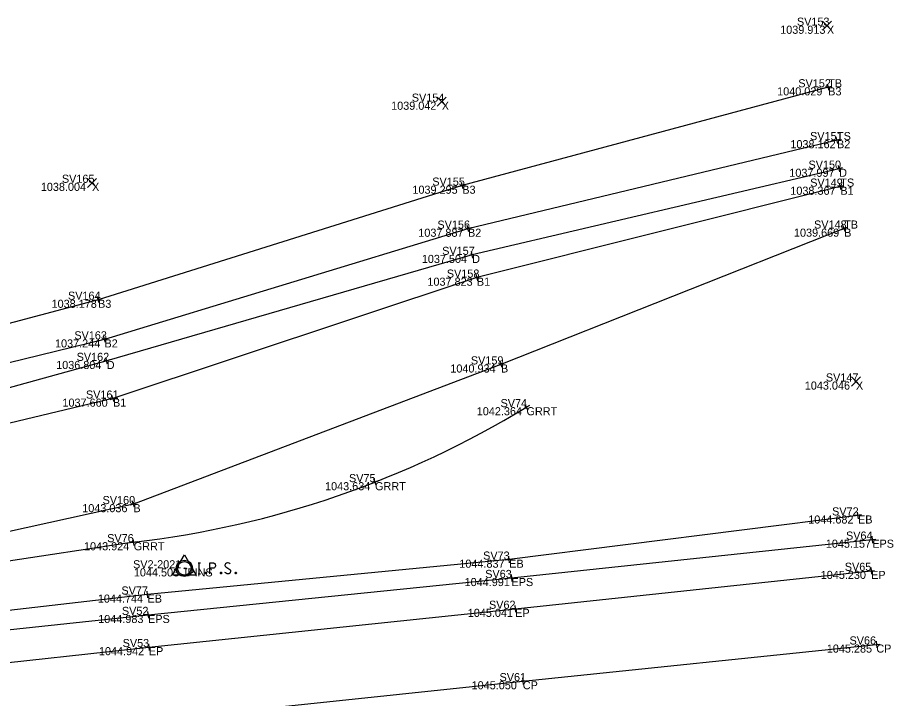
# Model space of a CAD drawing. Extents: x 1542529 to 1609210, y 587215 to 645373.
# Drawn here: x 1609069.9 to 1609199.5, y 645271.7 to 645372.6 of the extents above; entities that cross this region are included whole.
import ezdxf

# ---------------------------------------------------------------- set-up
doc = ezdxf.new("R2010")
doc.units = 0
for name, color, linetype in [('DR_X_Ditch', 7, 'Continuous'), ('PV_X_COP', 7, 'Continuous'), ('PV_X_EOP', 7, 'Continuous'), ('PV_X_Shoulder', 7, 'Continuous'), ('PV_X_Shoulder_Aggregate', 7, 'Continuous'), ('RD_X_GR_Rt', 7, 'Continuous'), ('SV_Control_Point', 7, 'Continuous'), ('SV_P_Mon_Cells_Set', 7, 'Continuous'), ('SV_X_Random_Point', 7, 'Continuous'), ('SV_X_Shot_Marker', 7, 'Continuous'), ('SV_X_Text_Comment', 7, 'Continuous'), ('SV_X_Text_Description', 7, 'Continuous'), ('SV_X_Text_Elevation', 7, 'Continuous'), ('SV_X_Text_Name', 7, 'Continuous'), ('SV_X_Toe_of_Slope', 7, 'Continuous'), ('SV_X_Top_of_Bank', 7, 'Continuous')]:
    doc.layers.add(name, color=color, linetype=linetype)

msp = doc.modelspace()

# ---------------------------------------------------------------- linework, layer by layer
at = {"layer": 'DR_X_Ditch'}
msp.add_lwpolyline([(1609191.48, 645350.17), (1609137.17, 645337.41), (1609083.09, 645321.71), (1609033.27, 645307.94), (1608983.73, 645297.77), (1608971.61, 645296.9)], dxfattribs=at)
at = {"layer": 'PV_X_COP'}
msp.add_lwpolyline([(1608977.96, 645256.77), (1609036.2, 645262.81), (1609089.9, 645268.52), (1609144.66, 645274.29), (1609196.98, 645279.72)], dxfattribs=at)
at = {"layer": 'PV_X_EOP'}
msp.add_lwpolyline([(1608980.54, 645267.46), (1609035.11, 645273.39), (1609089.32, 645279.34), (1609143.54, 645285.01), (1609196.2, 645290.63)], dxfattribs=at)
at = {"layer": 'PV_X_Shoulder'}
msp.add_lwpolyline([(1608982.3, 645272.44), (1609034.56, 645278.3), (1609089.21, 645284.1), (1609142.99, 645289.57), (1609196.38, 645295.25)], dxfattribs=at)
at = {"layer": 'PV_X_Shoulder_Aggregate'}
msp.add_lwpolyline([(1609194.27, 645298.83), (1609142.65, 645292.29), (1609089.13, 645287.12), (1609034.36, 645280.82), (1608983.09, 645274.8)], dxfattribs=at)
at = {"layer": 'RD_X_GR_Rt'}
msp.add_line((1609087.09, 645294.87), (1609034.27, 645286.84), dxfattribs=at)
msp.add_arc((1609070.49, 645437.62), 143.71, 276.6306, 301.327, dxfattribs=at)
at = {"layer": 'SV_Control_Point'}
for p, q in [((1609092.85, 645290), (1609094.58, 645293)), ((1609094.58, 645293), (1609096.32, 645290)), ((1609094.58, 645291), (1609094.58, 645291)), ((1609096.32, 645290), (1609092.85, 645290))]:
    msp.add_line(p, q, dxfattribs=at)
msp.add_circle((1609094.58, 645291), 1, dxfattribs=at)
at = {"layer": 'SV_P_Mon_Cells_Set'}
for points in [[(1609094.68, 645291.04), (1609094.7, 645291.04)], [(1609094.68, 645290.96), (1609094.7, 645290.96)], [(1609094.69, 645290.96), (1609094.69, 645291.04)], [(1609094.74, 645290.97), (1609094.74, 645290.97), (1609094.75, 645290.96), (1609094.75, 645290.96), (1609094.75, 645290.96), (1609094.75, 645290.96), (1609094.74, 645290.96), (1609094.74, 645290.96), (1609094.74, 645290.96), (1609094.74, 645290.96), (1609094.74, 645290.96), (1609094.74, 645290.96), (1609094.74, 645290.97)], [(1609094.77, 645290.96), (1609094.77, 645291.04), (1609094.8, 645291.04), (1609094.8, 645291.03), (1609094.81, 645291.03), (1609094.81, 645291.03), (1609094.81, 645291.03), (1609094.81, 645291.03), (1609094.81, 645291.02), (1609094.81, 645291.02), (1609094.81, 645291.01), (1609094.81, 645291.01), (1609094.81, 645291.01), (1609094.81, 645291), (1609094.81, 645291), (1609094.81, 645291), (1609094.8, 645291), (1609094.8, 645291), (1609094.77, 645291)], [(1609094.85, 645290.97), (1609094.86, 645290.97), (1609094.86, 645290.96), (1609094.86, 645290.96), (1609094.86, 645290.96), (1609094.86, 645290.96), (1609094.86, 645290.96), (1609094.85, 645290.96), (1609094.85, 645290.96), (1609094.85, 645290.96), (1609094.85, 645290.96), (1609094.85, 645290.96), (1609094.85, 645290.97)], [(1609094.92, 645291.03), (1609094.92, 645291.03), (1609094.92, 645291.03), (1609094.91, 645291.03), (1609094.91, 645291.04), (1609094.9, 645291.04), (1609094.9, 645291.04), (1609094.9, 645291.03), (1609094.89, 645291.03), (1609094.89, 645291.02), (1609094.88, 645291.02), (1609094.88, 645291.02), (1609094.89, 645291.01), (1609094.89, 645291.01), (1609094.92, 645290.99), (1609094.92, 645290.98), (1609094.92, 645290.98), (1609094.93, 645290.98), (1609094.93, 645290.97), (1609094.92, 645290.97), (1609094.92, 645290.97), (1609094.92, 645290.97), (1609094.92, 645290.96), (1609094.92, 645290.96), (1609094.92, 645290.96), (1609094.92, 645290.96), (1609094.92, 645290.96), (1609094.91, 645290.96), (1609094.91, 645290.96), (1609094.9, 645290.96), (1609094.9, 645290.96), (1609094.89, 645290.96), (1609094.88, 645290.96)], [(1609094.96, 645290.97), (1609094.97, 645290.97), (1609094.97, 645290.96), (1609094.97, 645290.96), (1609094.97, 645290.96), (1609094.97, 645290.96), (1609094.97, 645290.96), (1609094.96, 645290.96), (1609094.96, 645290.96), (1609094.96, 645290.96), (1609094.96, 645290.96), (1609094.96, 645290.96), (1609094.96, 645290.97)], [(1609096.6, 645291.8), (1609096.96, 645291.8)], [(1609096.78, 645290.2), (1609096.78, 645291.8)], [(1609098.34, 645290.2), (1609098.34, 645291.8), (1609098.87, 645291.8), (1609098.93, 645291.78), (1609099.01, 645291.76), (1609099.04, 645291.73), (1609099.07, 645291.71), (1609099.12, 645291.65), (1609099.15, 645291.58), (1609099.17, 645291.48), (1609099.17, 645291.33), (1609099.16, 645291.28), (1609099.14, 645291.2), (1609099.09, 645291.12), (1609099.05, 645291.08), (1609099.02, 645291.05), (1609098.96, 645291.03), (1609098.87, 645291.02), (1609098.34, 645291.02)], [(1609101.35, 645291.68), (1609101.33, 645291.71), (1609101.3, 645291.73), (1609101.2, 645291.77), (1609101.08, 645291.8), (1609100.99, 645291.8), (1609100.96, 645291.8), (1609100.81, 645291.76), (1609100.69, 645291.68), (1609100.62, 645291.58), (1609100.59, 645291.48), (1609100.59, 645291.41), (1609100.62, 645291.31), (1609100.7, 645291.22), (1609101.31, 645290.84), (1609101.36, 645290.79), (1609101.39, 645290.74), (1609101.41, 645290.66), (1609101.41, 645290.59), (1609101.4, 645290.51), (1609101.39, 645290.46), (1609101.36, 645290.4), (1609101.34, 645290.35), (1609101.32, 645290.31), (1609101.29, 645290.27), (1609101.25, 645290.25), (1609101.21, 645290.22), (1609101.18, 645290.21), (1609101.08, 645290.2), (1609100.92, 645290.2), (1609100.82, 645290.22), (1609100.68, 645290.31), (1609100.59, 645290.39)], [(1609096.6, 645290.2), (1609096.96, 645290.2)], [(1609097.74, 645290.41), (1609097.79, 645290.41), (1609097.83, 645290.39), (1609097.86, 645290.34), (1609097.86, 645290.27), (1609097.83, 645290.22), (1609097.79, 645290.2), (1609097.74, 645290.2), (1609097.71, 645290.22), (1609097.67, 645290.27), (1609097.67, 645290.34), (1609097.71, 645290.39), (1609097.74, 645290.41)], [(1609099.99, 645290.41), (1609100.04, 645290.41), (1609100.08, 645290.39), (1609100.11, 645290.34), (1609100.11, 645290.27), (1609100.08, 645290.22), (1609100.04, 645290.2), (1609099.99, 645290.2), (1609099.95, 645290.22), (1609099.92, 645290.27), (1609099.92, 645290.34), (1609099.95, 645290.39), (1609099.99, 645290.41)], [(1609102.17, 645290.41), (1609102.22, 645290.41), (1609102.26, 645290.39), (1609102.29, 645290.34), (1609102.29, 645290.27), (1609102.26, 645290.22), (1609102.22, 645290.2), (1609102.17, 645290.2), (1609102.14, 645290.22), (1609102.1, 645290.27), (1609102.1, 645290.34), (1609102.14, 645290.39), (1609102.17, 645290.41)]]:
    msp.add_lwpolyline(points, dxfattribs=at)
for radius in [1.2, 0.06]:
    msp.add_circle((1609094.58, 645291), radius, dxfattribs=at)
at = {"layer": 'SV_X_Random_Point'}
for p, q in [((1609189.01, 645370.67), (1609190.34, 645372)), ((1609189.01, 645372), (1609190.34, 645370.67)), ((1609132.01, 645359.42), (1609133.34, 645360.76)), ((1609132.01, 645360.76), (1609133.34, 645359.42)), ((1609080.25, 645347.41), (1609081.58, 645348.74)), ((1609080.25, 645348.74), (1609081.58, 645347.41)), ((1609193.29, 645317.99), (1609194.63, 645319.33)), ((1609193.29, 645319.33), (1609194.63, 645317.99))]:
    msp.add_line(p, q, dxfattribs=at)
at = {"layer": 'SV_X_Shot_Marker'}
for p, q in [((1609190.35, 645362.35), (1609189.38, 645362.09)), ((1609189.99, 645361.74), (1609189.73, 645362.7)), ((1609189.86, 645362.22), (1609189.86, 645362.22)), ((1609191.64, 645354.51), (1609190.67, 645354.28)), ((1609191.27, 645353.91), (1609191.04, 645354.88)), ((1609191.16, 645354.4), (1609191.16, 645354.4)), ((1609191.6, 645349.69), (1609191.37, 645350.66)), ((1609191.97, 645350.29), (1609191, 645350.06)), ((1609191.48, 645350.17), (1609191.48, 645350.17)), ((1609136.19, 645347.79), (1609135.23, 645347.53)), ((1609135.84, 645347.18), (1609135.58, 645348.14)), ((1609191.77, 645347.03), (1609191.53, 645348)), ((1609135.71, 645347.66), (1609135.71, 645347.66)), ((1609192.13, 645347.63), (1609191.16, 645347.39)), ((1609191.65, 645347.51), (1609191.65, 645347.51)), ((1609137.03, 645341.41), (1609136.06, 645341.17)), ((1609136.66, 645340.8), (1609136.43, 645341.78)), ((1609136.55, 645341.29), (1609136.55, 645341.29)), ((1609192.68, 645341.48), (1609191.75, 645341.11)), ((1609192.4, 645340.83), (1609192.03, 645341.76)), ((1609192.22, 645341.3), (1609192.22, 645341.3)), ((1609137.65, 645337.53), (1609136.68, 645337.3)), ((1609137.28, 645336.93), (1609137.05, 645337.9)), ((1609137.17, 645337.41), (1609137.17, 645337.41)), ((1609138.35, 645334.17), (1609137.38, 645333.92)), ((1609137.99, 645333.56), (1609137.75, 645334.53)), ((1609137.87, 645334.04), (1609137.87, 645334.04)), ((1609082.29, 645330.92), (1609081.33, 645330.62)), ((1609081.96, 645330.3), (1609081.66, 645331.25)), ((1609081.81, 645330.77), (1609081.81, 645330.77)), ((1609083.24, 645325.05), (1609082.28, 645324.76)), ((1609082.91, 645324.42), (1609082.62, 645325.38)), ((1609082.76, 645324.9), (1609082.76, 645324.9)), ((1609083.57, 645321.85), (1609082.61, 645321.57)), ((1609083.23, 645321.23), (1609082.95, 645322.19)), ((1609083.09, 645321.71), (1609083.09, 645321.71)), ((1609141.89, 645321.38), (1609140.96, 645321.01)), ((1609141.61, 645320.73), (1609141.24, 645321.66)), ((1609141.43, 645321.19), (1609141.43, 645321.19)), ((1609084.5, 645316.28), (1609083.55, 645315.97)), ((1609084.18, 645315.65), (1609083.87, 645316.6)), ((1609084.02, 645316.13), (1609084.02, 645316.13)), ((1609145.64, 645315.12), (1609144.78, 645314.6)), ((1609145.47, 645314.43), (1609144.95, 645315.28)), ((1609145.21, 645314.86), (1609145.21, 645314.86)), ((1609123.26, 645303.94), (1609122.33, 645303.58)), ((1609122.98, 645303.29), (1609122.61, 645304.23)), ((1609122.8, 645303.76), (1609122.8, 645303.76)), ((1609087.51, 645300.69), (1609086.58, 645300.34)), ((1609087.22, 645300.05), (1609086.87, 645300.98)), ((1609087.04, 645300.51), (1609087.04, 645300.51)), ((1609194.77, 645298.9), (1609193.78, 645298.77)), ((1609194.33, 645298.34), (1609194.21, 645299.33)), ((1609194.27, 645298.83), (1609194.27, 645298.83)), ((1609087.58, 645294.94), (1609086.59, 645294.79)), ((1609087.16, 645294.37), (1609087.01, 645295.36)), ((1609087.09, 645294.87), (1609087.09, 645294.87)), ((1609195.88, 645295.2), (1609196.88, 645295.3)), ((1609196.33, 645295.75), (1609196.43, 645294.75)), ((1609196.38, 645295.25), (1609196.38, 645295.25)), ((1609143.14, 645292.35), (1609142.15, 645292.23)), ((1609142.71, 645291.79), (1609142.58, 645292.78)), ((1609142.65, 645292.29), (1609142.65, 645292.29)), ((1609196.15, 645291.13), (1609196.25, 645290.13)), ((1609142.5, 645289.52), (1609143.49, 645289.62)), ((1609142.94, 645290.07), (1609143.04, 645289.07)), ((1609142.99, 645289.57), (1609142.99, 645289.57)), ((1609195.7, 645290.58), (1609196.7, 645290.69)), ((1609196.2, 645290.63), (1609196.2, 645290.63)), ((1609089.62, 645287.17), (1609088.63, 645287.07)), ((1609089.17, 645286.62), (1609089.08, 645287.62)), ((1609089.13, 645287.12), (1609089.13, 645287.12)), ((1609143.49, 645285.51), (1609143.59, 645284.51)), ((1609089.15, 645284.6), (1609089.26, 645283.61)), ((1609143.04, 645284.96), (1609144.04, 645285.06)), ((1609143.54, 645285.01), (1609143.54, 645285.01)), ((1609088.71, 645284.05), (1609089.7, 645284.16)), ((1609089.21, 645284.1), (1609089.21, 645284.1)), ((1609088.82, 645279.28), (1609089.82, 645279.39)), ((1609089.27, 645279.84), (1609089.38, 645278.84)), ((1609089.32, 645279.34), (1609089.32, 645279.34)), ((1609196.48, 645279.66), (1609197.48, 645279.77)), ((1609196.93, 645280.21), (1609197.03, 645279.22)), ((1609196.98, 645279.72), (1609196.98, 645279.72)), ((1609144.16, 645274.24), (1609145.16, 645274.34)), ((1609144.61, 645274.79), (1609144.71, 645273.79)), ((1609144.66, 645274.29), (1609144.66, 645274.29))]:
    msp.add_line(p, q, dxfattribs=at)
at = {"layer": 'SV_X_Toe_of_Slope'}
for points in [[(1609191.16, 645354.4), (1609136.55, 645341.29), (1609082.76, 645324.9), (1609032.73, 645312.65), (1608984.25, 645301.38), (1608971.44, 645300.51)], [(1609191.65, 645347.51), (1609137.87, 645334.04), (1609084.02, 645316.13), (1609033.5, 645304.05), (1608983.85, 645295.62), (1608970.47, 645287.32)]]:
    msp.add_lwpolyline(points, dxfattribs=at)
at = {"layer": 'SV_X_Top_of_Bank'}
for points in [[(1609189.86, 645362.22), (1609135.71, 645347.66), (1609081.81, 645330.77), (1609032.04, 645317.53), (1608983.35, 645307.89), (1608972.26, 645304.11), (1608947.01, 645307.47), (1608960.75, 645337.44)], [(1609192.22, 645341.3), (1609141.43, 645321.19), (1609087.04, 645300.51), (1609033.08, 645288.6), (1608989.08, 645281.09)]]:
    msp.add_lwpolyline(points, dxfattribs=at)

# ---------------------------------------------------------------- texts
at = {"layer": 'SV_X_Text_Comment'}
for s, p in [('X', (1609189.67, 645370.14)), ('B3', (1609189.86, 645361.02)), ('X', (1609132.67, 645358.89)), ('B2', (1609191.16, 645353.2)), ('D', (1609191.48, 645348.97)), ('X', (1609080.92, 645346.88)), ('B3', (1609135.71, 645346.46)), ('B1', (1609191.65, 645346.31)), ('B2', (1609136.55, 645340.09)), ('B', (1609192.22, 645340.1)), ('D', (1609137.17, 645336.21)), ('B1', (1609137.87, 645332.84)), ('B3', (1609081.81, 645329.57)), ('B2', (1609082.76, 645323.7)), ('D', (1609083.09, 645320.51)), ('B', (1609141.43, 645319.99)), ('X', (1609193.96, 645317.46)), ('B1', (1609084.02, 645314.93)), ('GRRT', (1609145.21, 645313.66)), ('GRRT', (1609122.8, 645302.56)), ('B', (1609087.04, 645299.31)), ('EB', (1609194.27, 645297.63)), ('GRRT', (1609087.09, 645293.67)), ('EPS', (1609196.38, 645294.05)), ('EB', (1609142.65, 645291.09)), ('IPINS', (1609094.58, 645289.8)), ('EPS', (1609142.99, 645288.37)), ('EP', (1609196.2, 645289.43)), ('EB', (1609089.13, 645285.92)), ('EP', (1609143.54, 645283.81)), ('EPS', (1609089.21, 645282.9)), ('EP', (1609089.32, 645278.14)), ('CP', (1609196.98, 645278.52)), ('CP', (1609144.66, 645273.09))]:
    msp.add_text(s, height=1.2, dxfattribs=at).set_placement(p)
at = {"layer": 'SV_X_Text_Description'}
for s, p in [('TB', (1609189.86, 645362.22)), ('TS', (1609191.16, 645354.4)), ('TS', (1609191.65, 645347.51)), ('TB', (1609192.22, 645341.3))]:
    msp.add_text(s, height=1.2, dxfattribs=at).set_placement(p)
at = {"layer": 'SV_X_Text_Elevation'}
for s, height, p in [('1039.913', 1.2, (1609182.75, 645370.14)), ('1040.029', 1.2, (1609182.3, 645361.02)), ('1039.042', 1.2, (1609125.18, 645358.89)), ('1038.162', 1.2, (1609184.26, 645353.2)), ('1037.997', 1.2, (1609184.1, 645348.97)), ('1038.004', 1.2, (1609073.34, 645346.88)), ('1039.295', 1.2, (1609128.33, 645346.46)), ('1038.367', 1.2, (1609184.25, 645346.31)), ('1037.887', 1.2, (1609129.2, 645340.09)), ('1039.669', 1.2, (1609184.79, 645340.1)), ('1037.504', 1.2, (1609129.72, 645336.21)), ('1037.823', 1.2, (1609130.55, 645332.84)), ('1038.178', 1.2, (1609074.93, 645329.57)), ('1037.244', 1.2, (1609075.44, 645323.7)), ('1036.804', 1.2, (1609075.61, 645320.51)), ('1040.934', 1.2, (1609133.94, 645319.99)), ('1043.046', 1.2, (1609186.39, 645317.46)), ('1037.660', 1.2, (1609076.54, 645314.93)), ('1042.364', 1.2, (1609137.85, 645313.66)), ('1043.634', 1.2, (1609115.4, 645302.56)), ('1043.036', 1.2, (1609079.47, 645299.31)), ('1044.682', 1.2, (1609186.9, 645297.63)), ('1043.924', 1.2, (1609079.73, 645293.67)), ('1045.157', 1.2, (1609189.5, 645294.05)), ('1044.837', 1.2, (1609135.27, 645291.09)), ('1044.503', 1.2, (1609087.11, 645289.8)), ('1044.50', 0.06, (1609094.26, 645290.94)), ('1044.991', 1.2, (1609136.05, 645288.37)), ('1045.230', 1.2, (1609188.75, 645289.43)), ('1044.744', 1.2, (1609081.78, 645285.92)), ('1045.041', 1.2, (1609136.52, 645283.81)), ('1044.983', 1.2, (1609081.83, 645282.9)), ('1044.942', 1.2, (1609081.94, 645278.14)), ('1045.285', 1.2, (1609189.65, 645278.52)), ('1045.050', 1.2, (1609137.09, 645273.09))]:
    msp.add_text(s, height=height, dxfattribs=at).set_placement(p)
at = {"layer": 'SV_X_Text_Name'}
for s, height, p in [('SV153', 1.2, (1609185.23, 645371.34)), ('SV152', 1.2, (1609185.43, 645362.22)), ('SV154', 1.2, (1609128.24, 645360.09)), ('SV151', 1.2, (1609187.17, 645354.4)), ('SV150', 1.2, (1609186.94, 645350.17)), ('SV165', 1.2, (1609076.46, 645348.08)), ('SV155', 1.2, (1609131.27, 645347.66)), ('SV149', 1.2, (1609187.19, 645347.51)), ('SV156', 1.2, (1609132.03, 645341.29)), ('SV148', 1.2, (1609187.76, 645341.3)), ('SV157', 1.2, (1609132.73, 645337.41)), ('SV158', 1.2, (1609133.42, 645334.04)), ('SV164', 1.2, (1609077.36, 645330.77)), ('SV163', 1.2, (1609078.3, 645324.9)), ('SV162', 1.2, (1609078.64, 645321.71)), ('SV159', 1.2, (1609136.98, 645321.19)), ('SV147', 1.2, (1609189.51, 645318.66)), ('SV161', 1.2, (1609080.02, 645316.13)), ('SV74', 1.2, (1609141.37, 645314.86)), ('SV75', 1.2, (1609118.94, 645303.76)), ('SV160', 1.2, (1609082.48, 645300.51)), ('SV72', 1.2, (1609190.43, 645298.83)), ('SV76', 1.2, (1609083.16, 645294.87)), ('SV64', 1.2, (1609192.49, 645295.25)), ('SV73', 1.2, (1609138.79, 645292.29)), ('SV2-2021', 1.2, (1609086.99, 645291)), ('SV22021', 0.06, (1609094.25, 645291)), ('SV63', 1.2, (1609139.1, 645289.57)), ('SV65', 1.2, (1609192.31, 645290.63)), ('SV77', 1.2, (1609085.27, 645287.12)), ('SV62', 1.2, (1609139.66, 645285.01)), ('SV52', 1.2, (1609085.34, 645284.1)), ('SV53', 1.2, (1609085.45, 645279.34)), ('SV66', 1.2, (1609193.01, 645279.72)), ('SV61', 1.2, (1609141.22, 645274.29))]:
    msp.add_text(s, height=height, dxfattribs=at).set_placement(p)

doc.saveas('drawing.dxf')
